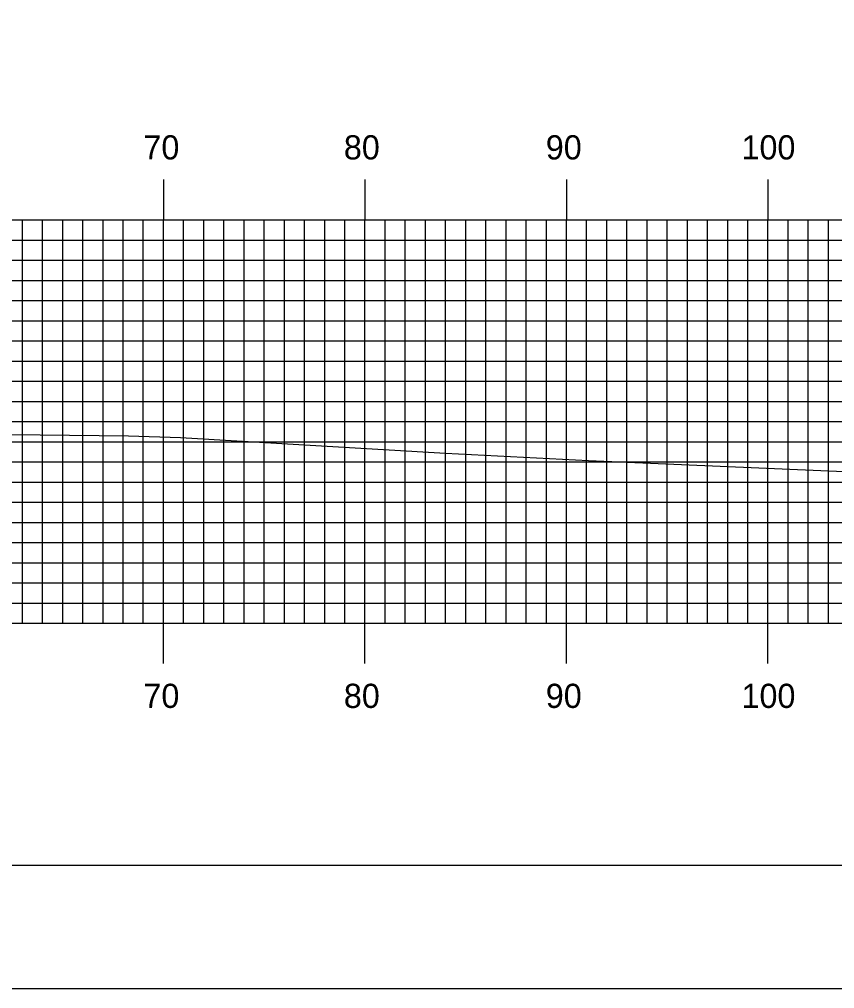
# Model space of a CAD drawing. Extents: x 1774777 to 1775120, y 442591 to 442811.
# Drawn here: x 1775005.53 to 1775045.99, y 442590.55 to 442638.61 of the extents above; entities that cross this region are included whole.
import ezdxf

# ---------------------------------------------------------------- set-up
doc = ezdxf.new("R2010")
doc.units = 0
for name, color, linetype in [('BORDER', 7, 'Continuous'), ('H_V ANNOTATION', 7, 'Continuous'), ('MAJOR', 7, 'Continuous'), ('MINOR', 7, 'Continuous'), ('PLOT BOUNDARY', 7, 'Continuous'), ('S_Roadway_Centerline', 7, 'Continuous')]:
    doc.layers.add(name, color=color, linetype=linetype)

msp = doc.modelspace()

# ---------------------------------------------------------------- linework, layer by layer
at = {"layer": 'BORDER'}
msp.add_lwpolyline([(1774793.085, 442596.665), (1775113.085, 442596.665), (1775113.085, 442806.665), (1774793.085, 442806.665)], close=True, dxfattribs=at)
at = {"layer": 'MAJOR'}
for p, q in [((1775012.685, 442630.669), (1775012.685, 442628.665)), ((1775022.685, 442630.669), (1775022.685, 442628.665)), ((1775032.685, 442630.669), (1775032.685, 442628.665)), ((1775042.685, 442630.669), (1775042.685, 442628.665)), ((1774802.685, 442628.665), (1775082.685, 442628.665)), ((1774802.685, 442628.665), (1775082.685, 442628.665)), ((1775012.685, 442608.665), (1775012.685, 442628.665)), ((1775022.685, 442608.665), (1775022.685, 442628.665)), ((1775032.685, 442608.665), (1775032.685, 442628.665)), ((1775042.685, 442608.665), (1775042.685, 442628.665)), ((1774802.685, 442623.665), (1775082.685, 442623.665)), ((1774802.685, 442618.665), (1775082.685, 442618.665)), ((1774802.685, 442613.665), (1775082.685, 442613.665)), ((1774802.685, 442608.665), (1775082.685, 442608.665)), ((1774802.685, 442608.665), (1775082.685, 442608.665)), ((1775012.685, 442606.661), (1775012.685, 442608.665)), ((1775022.685, 442606.661), (1775022.685, 442608.665)), ((1775032.685, 442606.661), (1775032.685, 442608.665)), ((1775042.685, 442606.661), (1775042.685, 442608.665))]:
    msp.add_line(p, q, dxfattribs=at)
at = {"layer": 'MINOR'}
for p, q in [((1775005.685, 442608.665), (1775005.685, 442628.665)), ((1775006.685, 442608.665), (1775006.685, 442628.665)), ((1775007.685, 442608.665), (1775007.685, 442628.665)), ((1775008.685, 442608.665), (1775008.685, 442628.665)), ((1775009.685, 442608.665), (1775009.685, 442628.665)), ((1775010.685, 442608.665), (1775010.685, 442628.665)), ((1775011.685, 442608.665), (1775011.685, 442628.665)), ((1775013.685, 442608.665), (1775013.685, 442628.665)), ((1775014.685, 442608.665), (1775014.685, 442628.665)), ((1775015.685, 442608.665), (1775015.685, 442628.665)), ((1775016.685, 442608.665), (1775016.685, 442628.665)), ((1775017.685, 442608.665), (1775017.685, 442628.665)), ((1775018.685, 442608.665), (1775018.685, 442628.665)), ((1775019.685, 442608.665), (1775019.685, 442628.665)), ((1775020.685, 442608.665), (1775020.685, 442628.665)), ((1775021.685, 442608.665), (1775021.685, 442628.665)), ((1775023.685, 442608.665), (1775023.685, 442628.665)), ((1775024.685, 442608.665), (1775024.685, 442628.665)), ((1775025.685, 442608.665), (1775025.685, 442628.665)), ((1775026.685, 442608.665), (1775026.685, 442628.665)), ((1775027.685, 442608.665), (1775027.685, 442628.665)), ((1775028.685, 442608.665), (1775028.685, 442628.665)), ((1775029.685, 442608.665), (1775029.685, 442628.665)), ((1775030.685, 442608.665), (1775030.685, 442628.665)), ((1775031.685, 442608.665), (1775031.685, 442628.665)), ((1775033.685, 442608.665), (1775033.685, 442628.665)), ((1775034.685, 442608.665), (1775034.685, 442628.665)), ((1775035.685, 442608.665), (1775035.685, 442628.665)), ((1775036.685, 442608.665), (1775036.685, 442628.665)), ((1775037.685, 442608.665), (1775037.685, 442628.665)), ((1775038.685, 442608.665), (1775038.685, 442628.665)), ((1775039.685, 442608.665), (1775039.685, 442628.665)), ((1775040.685, 442608.665), (1775040.685, 442628.665)), ((1775041.685, 442608.665), (1775041.685, 442628.665)), ((1775043.685, 442608.665), (1775043.685, 442628.665)), ((1775044.685, 442608.665), (1775044.685, 442628.665)), ((1775045.685, 442608.665), (1775045.685, 442628.665)), ((1774802.685, 442627.665), (1775082.685, 442627.665)), ((1774802.685, 442626.665), (1775082.685, 442626.665)), ((1774802.685, 442625.665), (1775082.685, 442625.665)), ((1774802.685, 442624.665), (1775082.685, 442624.665)), ((1774802.685, 442622.665), (1775082.685, 442622.665)), ((1774802.685, 442621.665), (1775082.685, 442621.665)), ((1774802.685, 442620.665), (1775082.685, 442620.665)), ((1774802.685, 442619.665), (1775082.685, 442619.665)), ((1774802.685, 442617.665), (1775082.685, 442617.665)), ((1774802.685, 442616.665), (1775082.685, 442616.665)), ((1774802.685, 442615.665), (1775082.685, 442615.665)), ((1774802.685, 442614.665), (1775082.685, 442614.665)), ((1774802.685, 442612.665), (1775082.685, 442612.665)), ((1774802.685, 442611.665), (1775082.685, 442611.665)), ((1774802.685, 442610.665), (1775082.685, 442610.665)), ((1774802.685, 442609.665), (1775082.685, 442609.665))]:
    msp.add_line(p, q, dxfattribs=at)
at = {"layer": 'PLOT BOUNDARY'}
msp.add_lwpolyline([(1774776.898, 442590.547), (1775116.898, 442590.547), (1775116.898, 442810.547), (1774776.898, 442810.547)], close=True, dxfattribs=at)
at = {"layer": 'S_Roadway_Centerline'}
msp.add_lwpolyline([(1775000.697, 442618.077), (1775010.952, 442617.962), (1775013.522, 442617.881), (1775026.675, 442617.107), (1775033.775, 442616.742), (1775046.843, 442616.175), (1775055.308, 442615.876), (1775061.468, 442615.86), (1775078.187, 442615.666), (1775082.685, 442615.47)], dxfattribs=at)

# ---------------------------------------------------------------- texts
at = {"layer": 'H_V ANNOTATION'}
for s, p in [('70', (1775011.689, 442631.665)), ('80', (1775021.636, 442631.665)), ('90', (1775031.657, 442631.665)), ('100', (1775041.369, 442631.665)), ('70', (1775011.689, 442604.465)), ('80', (1775021.636, 442604.465)), ('90', (1775031.657, 442604.465)), ('100', (1775041.369, 442604.465))]:
    msp.add_text(s, height=1.2, dxfattribs=at).set_placement(p)

doc.saveas('drawing.dxf')
